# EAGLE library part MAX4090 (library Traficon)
3V/5V, 6dB Video Buffer with Sync-Tip Clamp and 150nA Shutdown Current
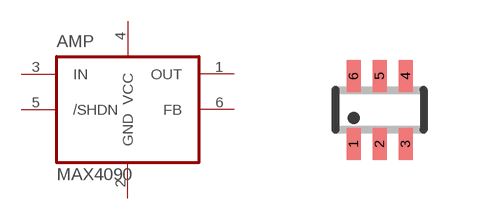
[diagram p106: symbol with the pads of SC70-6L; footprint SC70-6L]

Designator prefix AMP

## MAX4090AAXT-T  [SC70-6L]
1  OUT
2  GND
3  IN
4  VCC
5  /SHDN
6  FB

## Footprint SC70-6L (pad centres in mm)
SC-70 Package
smd 0.35 x 0.8: 1 -0.65,-0.85; 2 0,-0.85; 3 0.65,-0.85; 4 0.65,0.85; 5 0,0.85; 6 -0.65,0.85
